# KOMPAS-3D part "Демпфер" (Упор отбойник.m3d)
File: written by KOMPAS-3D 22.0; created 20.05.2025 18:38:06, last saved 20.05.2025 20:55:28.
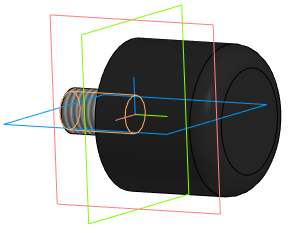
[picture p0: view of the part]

Document properties: Автор: user; Полное имя файла: D:\Работа\2025\5. Май\Задание №6 - Тележка для крыши\3Д\Упор отбойник.m3d

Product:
- Body: Тело 1
    Масса: 1.276261
- Part/product: Демпфер
    Масса: 1.293891
- Part/product: Демпфер покупной
    Масса: 0.356039

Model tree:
1. Эскиз:1
2. Элемент выдавливания:1
     Расстояние 1 = 130
3. Эскиз:2  (with: Элемент выдавливания:1)
4. Элемент вращения:1  (with: Элемент выдавливания:1)
     Угол 1 = 360
5. Скругление:1  (with: Элемент выдавливания:1)
     Радиус = 6
6. Эскиз:3  (with: Элемент выдавливания:1)
7. Элемент выдавливания:2
     Расстояние 1 = 20
8. Фаска:1  (with: Элемент выдавливания:2)
     Угол = 45; Длина 1 = 1; Длина 2 = 1
9. Условное изображение резьбы:1  (with: Элемент выдавливания:2, Фаска:1)  (labels: M12; cil0_24705-2004 coarse)
     Длина резьбы = 20; Шаг резьбы = 1.75; Номинальный диаметр резьбы = 12
10. Подгонка:1  (with: Фаска:1, Элемент выдавливания:2)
